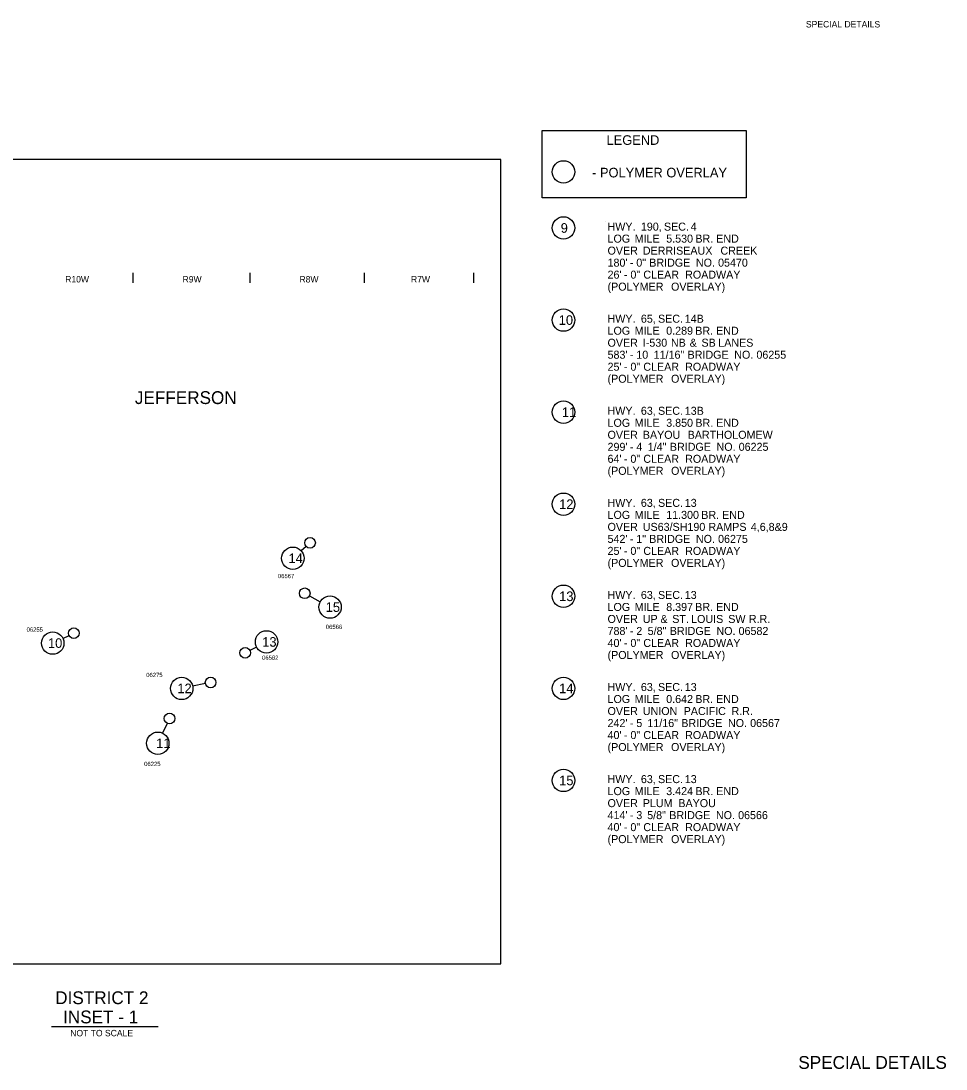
# Model space of a CAD drawing. Extents: x -33639 to 34530, y -17264 to 5867.
# Drawn here: x 8232 to 16899, y -4264 to 5557 of the extents above; entities that cross this region are included whole.
import ezdxf

# ---------------------------------------------------------------- set-up
doc = ezdxf.new("R2010")
doc.units = 0
for name, color, linetype in [('2', 7, 'Continuous'), ('Default', 7, 'Continuous'), ('R_Annotation', 7, 'Continuous'), ('R_Border', 7, 'Continuous'), ('R_No Plot', 7, 'Continuous'), ('S_MISC_BOUNDARY', 7, 'Continuous')]:
    doc.layers.add(name, color=color, linetype=linetype)

msp = doc.modelspace()

# ---------------------------------------------------------------- linework, layer by layer
at = {"layer": 'Default'}
for p, q in [((9280.2, 3197.5), (9280.2, 3102.5)), ((10375.4, 3197.5), (10375.4, 3102.5)), ((11446.3, 3197.5), (11446.3, 3102.5)), ((12473, 3197.5), (12473, 3102.5))]:
    msp.add_line(p, q, dxfattribs=at)
at = {"layer": 'R_Annotation'}
for p, q in [((10903.3, 633.6), (10857.3, 592.2)), ((10934.6, 170.1), (11035.4, 115.2)), ((8624.6, -228.1), (8682.3, -201.2)), ((10439.3, -309.3), (10376.6, -341.2)), ((9960, -651.8), (9840.6, -676.1)), ((9602.8, -1024.8), (9558.9, -1117)), ((8517.6, -3866.6), (9517.6, -3866.6))]:
    msp.add_line(p, q, dxfattribs=at)
msp.add_lwpolyline([(13114.7, 4532.1), (15025.4, 4532.1), (15025.4, 3898.4), (13114.7, 3898.4)], close=True, dxfattribs=at)
for centre, radius in [((13314.9, 4142.6), 105), ((13314.9, 3617.5), 105), ((13314.9, 2754.6), 105), ((13314.9, 1891.7), 105), ((13314.9, 1028.8), 105), ((10940.5, 667), 50), ((10779.1, 522), 105), ((10890.7, 194), 50), ((13314.9, 166), 105), ((11127.6, 65), 105), ((8529.4, -272.5), 105), ((8727.6, -180), 50), ((10532.9, -261.7), 105), ((10332, -363.9), 50), ((9737.8, -697.1), 105), ((10009, -641.8), 50), ((13314.9, -696.9), 105), ((9624.3, -979.6), 50), ((9513.7, -1211.7), 105), ((13314.9, -1559.8), 105)]:
    msp.add_circle(centre, radius, dxfattribs=at)
at = {"layer": 'R_No Plot'}
msp.add_lwpolyline([(12727.1, 4259.5), (5331.1, 4259.5), (5331.1, -3279.5), (12727.1, -3279.5)], close=True, dxfattribs=at)
at = {"layer": 'S_MISC_BOUNDARY'}
for p, q in [((13713.1, 3682.6), (13713.1, 3682.6)), ((13727.7, -1509.7), (13727.7, -1509.7))]:
    msp.add_line(p, q, dxfattribs=at)

# ---------------------------------------------------------------- texts
at = {"layer": '2'}
for s, height, p in [('R10W', 60, (8646.5, 3106.7)), ('R9W', 60, (9746.2, 3106.7)), ('R8W', 60, (10841.3, 3106.7)), ('R7W', 60, (11886.1, 3106.7)), ('JEFFERSON', 120, (9299.1, 1967.6))]:
    msp.add_text(s, height=height, dxfattribs=at).set_placement(p)
at = {"layer": 'Default'}
for s, p in [('HWY.', (13727.7, 3592.6)), (' 190,', (14012, 3592.6)), (' SEC.', (14228, 3592.6)), (' 4', (14478.6, 3592.6)), ('LOG', (13727.7, 3480.1)), (' MILE', (13953.7, 3480.1)), (' 5.530', (14249.5, 3480.1)), (' BR.', (14522.5, 3480.1)), (' END', (14717.8, 3480.1)), ('OVER', (13727.7, 3367.6)), (' DERRISEAUX', (14030.2, 3367.6)), (' CREEK', (14757.9, 3367.6)), ("180'", (13727.7, 3255.1)), (' -', (13909.2, 3255.1)), (' 0"', (13969.4, 3255.1)), (' BRIDGE', (14090.5, 3255.1)), (' NO.', (14527.8, 3255.1)), (' 05470', (14735.3, 3255.1)), ("26'", (13727.7, 3142.6)), (' -', (13853.8, 3142.6)), (' 0"', (13914, 3142.6)), (' CLEAR', (14035, 3142.6)), (' ROADWAY', (14426.7, 3142.6)), ('(POLYMER', (13727.7, 3030.1)), (' OVERLAY)', (14294.8, 3030.1)), ('HWY.', (13727.7, 2729.7)), (' 65,', (14012, 2729.7)), (' SEC.', (14172.6, 2729.7)), (' 14B', (14423.2, 2729.7)), ('LOG', (13727.7, 2617.2)), (' MILE', (13953.7, 2617.2)), (' 0.289', (14249.5, 2617.2)), (' BR.', (14521.8, 2617.2)), (' END', (14717, 2617.2)), ('OVER', (13727.7, 2504.7)), (' I-530', (14030.2, 2504.7)), (' NB', (14293.9, 2504.7)), (' &', (14469.5, 2504.7)), (' SB', (14580, 2504.7)), (' LANES', (14737.1, 2504.7)), ("583'", (13727.7, 2392.2)), (' 10', (13969.4, 2392.2)), ('  11/16"', (14104, 2392.2)), (' BRIDGE', (14449.7, 2392.2)), (' NO.', (14887.1, 2392.2)), (' 06255', (15094.5, 2392.2)), (' -', (13909.2, 2392.2)), ("25'", (13727.7, 2279.7)), (' -', (13853.8, 2279.7)), (' 0"', (13914, 2279.7)), (' CLEAR', (14035, 2279.7)), (' ROADWAY', (14426.7, 2279.7)), ('(POLYMER', (13727.7, 2167.2)), (' OVERLAY)', (14294.8, 2167.2)), ('HWY.', (13727.7, 1866.8)), (' 63,', (14012, 1866.8)), (' SEC.', (14172.6, 1866.8)), (' 13B', (14423.2, 1866.8)), ('LOG', (13727.7, 1754.3)), (' MILE', (13953.7, 1754.3)), (' 3.850', (14249.5, 1754.3)), (' BR.', (14522.5, 1754.3)), (' END', (14717.8, 1754.3)), ('OVER', (13727.7, 1641.8)), (' BAYOU', (14030.2, 1641.8)), (' BARTHOLOMEW', (14450.4, 1641.8)), ("299'", (13727.7, 1529.3)), (' 4', (13969.4, 1529.3)), ('  1/4"', (14048.7, 1529.3)), (' BRIDGE', (14283.6, 1529.3)), (' NO.', (14720.9, 1529.3)), (' 06225', (14928.4, 1529.3)), ("64'", (13727.7, 1416.8)), (' -', (13909.2, 1529.3)), (' 0"', (13914, 1416.8)), (' CLEAR', (14035, 1416.8)), (' ROADWAY', (14426.7, 1416.8)), ('(POLYMER', (13727.7, 1304.3)), (' -', (13853.8, 1416.8)), (' OVERLAY)', (14294.8, 1304.3)), ('HWY.', (13727.7, 1003.9)), (' 63,', (14012, 1003.9)), (' SEC.', (14172.6, 1003.9)), (' 13', (14423.2, 1003.9)), ('LOG', (13727.7, 891.4)), (' MILE', (13953.7, 891.4)), (' 11.300', (14249.5, 891.4)), (' BR.', (14578, 891.4)), (' END', (14773.2, 891.4)), ('OVER', (13727.7, 778.9)), (' US63/SH190', (14030.2, 778.9)), (' RAMPS', (14644.9, 778.9)), (' 4,6,8&9', (15042.2, 778.9)), ("542'", (13727.7, 666.4)), (' -', (13909.2, 666.4)), (' 1"', (13969.4, 666.4)), (' BRIDGE', (14090.5, 666.4)), (' NO.', (14527.8, 666.4)), (' 06275', (14735.3, 666.4)), ("25'", (13727.7, 553.9)), (' 0"', (13914, 553.9)), (' CLEAR', (14035, 553.9)), (' ROADWAY', (14426.7, 553.9)), ('(POLYMER', (13727.7, 441.4)), (' -', (13853.8, 553.9)), (' OVERLAY)', (14294.8, 441.4)), ('HWY.', (13727.7, 141.1)), (' 63,', (14012, 141.1)), (' SEC.', (14172.6, 141.1)), (' 13', (14423.2, 141.1)), ('LOG', (13727.7, 28.6)), (' MILE', (13953.7, 28.6)), (' 8.397', (14249.5, 28.6)), (' BR.', (14521.5, 28.6)), (' END', (14716.8, 28.6)), ('OVER', (13727.7, -83.9)), (' UP', (14030.2, -83.9)), (' &', (14195.5, -83.9)), (' ST.', (14306, -83.9)), (' LOUIS', (14482.8, -83.9)), (' SW', (14830.7, -83.9)), (' R.R.', (15023.6, -83.9)), ("788'", (13727.7, -196.4)), (' -', (13909.2, -196.4)), (' 2', (13969.4, -196.4)), ('  5/8"', (14047.9, -196.4)), (' BRIDGE', (14282.8, -196.4)), (' NO.', (14720.2, -196.4)), (' 06582', (14927.6, -196.4)), ("40'", (13727.7, -308.9)), (' -', (13853.8, -308.9)), (' 0"', (13914, -308.9)), (' CLEAR', (14035, -308.9)), (' ROADWAY', (14426.7, -308.9)), ('(POLYMER', (13727.7, -421.4)), (' OVERLAY)', (14294.8, -421.4)), ('HWY.', (13727.7, -721.8)), (' 63,', (14012, -721.8)), (' SEC.', (14172.6, -721.8)), (' 13', (14423.2, -721.8)), ('LOG', (13727.7, -834.3)), (' MILE', (13953.7, -834.3)), (' 0.642', (14249.5, -834.3)), (' BR.', (14521.9, -834.3)), (' END', (14717.1, -834.3)), ('OVER', (13727.7, -946.8)), (' UNION', (14030.2, -946.8)), (' PACIFIC', (14413, -946.8)), (' R.R.', (14861.5, -946.8)), ('  11/16"', (14045.2, -1059.3)), ("242'", (13727.7, -1059.3)), (' -', (13909.2, -1059.3)), (' 5', (13969.4, -1059.3)), (' BRIDGE', (14390.9, -1059.3)), (' NO.', (14828.3, -1059.3)), (' 06567', (15035.7, -1059.3)), ("40'", (13727.7, -1171.8)), (' -', (13853.8, -1171.8)), (' 0"', (13914, -1171.8)), (' CLEAR', (14035, -1171.8)), (' ROADWAY', (14426.7, -1171.8)), ('(POLYMER', (13727.7, -1284.3)), (' OVERLAY)', (14294.8, -1284.3)), ('HWY.', (13727.7, -1584.7)), (' 63,', (14012, -1584.7)), (' SEC.', (14172.6, -1584.7)), (' 13', (14423.2, -1584.7)), ('LOG', (13727.7, -1697.2)), (' MILE', (13953.7, -1697.2)), (' 3.424', (14249.5, -1697.2)), (' BR.', (14522.7, -1697.2)), (' END', (14717.9, -1697.2)), ('OVER', (13727.7, -1809.7)), (' PLUM', (14030.2, -1809.7)), (' BAYOU', (14363.2, -1809.7)), ("414'", (13727.7, -1922.2)), (' 3', (13969.4, -1922.2)), ('  5/8"', (14043.3, -1922.2)), (' BRIDGE', (14278.2, -1922.2)), (' NO.', (14715.6, -1922.2)), (' 06566', (14923, -1922.2)), ("40'", (13727.7, -2034.7)), (' -', (13909.2, -1922.2)), (' 0"', (13914, -2034.7)), (' CLEAR', (14035, -2034.7)), (' ROADWAY', (14426.7, -2034.7)), (' -', (13853.8, -2034.7)), ('(POLYMER', (13727.7, -2147.2)), (' OVERLAY)', (14294.8, -2147.2))]:
    msp.add_text(s, height=75, dxfattribs=at).set_placement(p)
at = {"layer": 'R_Annotation'}
for s, height, p in [('LEGEND', 90, (13718.1, 4396.3)), ('- POLYMER OVERLAY', 90, (13583, 4091.3)), ('9', 90, (13289, 3572.5)), ('10', 90, (13270.6, 2709.6)), ('11', 90, (13300, 1846.7)), ('12', 90, (13274.5, 983.8)), ('14', 90, (10738.7, 477)), ('13', 90, (13274.5, 121)), ('15', 90, (11087.2, 20)), ('10', 90, (8485.1, -317.5)), ('13', 90, (10492.5, -306.7)), ('12', 90, (9697.4, -742.1)), ('14', 90, (13274.5, -741.9)), ('11', 90, (9498.8, -1256.7)), ('15', 90, (13274.5, -1604.8)), ('DISTRICT 2', 120, (8552.9, -3656)), ('INSET - 1', 120, (8626.6, -3836)), ('NOT TO SCALE', 60, (8693.7, -3957.3)), ('SPECIAL DETAILS', 120, (15515, -4262.4))]:
    msp.add_text(s, height=height, dxfattribs=at).set_placement(p)
at = {"layer": 'R_Border'}
msp.add_text('SPECIAL DETAILS', height=60, dxfattribs=at).set_placement((15586.1, 5496.5))
at = {"layer": 'R_No Plot'}
for s, p in [('06567', (10639.2, 335.8)), ('06255', (8284.5, -165.6)), ('06566', (11088.2, -140.4)), ('06582', (10490.7, -429.3)), ('06275', (9405.6, -591.2)), ('06225', (9385.9, -1424.9))]:
    msp.add_text(s, height=40, dxfattribs=at).set_placement(p)

doc.saveas('drawing.dxf')
